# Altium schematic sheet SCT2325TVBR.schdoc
size 127 x 101 mm
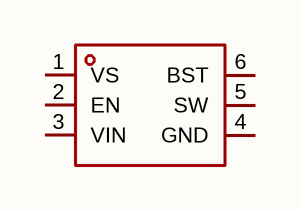
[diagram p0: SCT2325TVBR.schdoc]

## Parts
U?  sct2325tvbr  [TSOT-23-6_L2.9-W1.6-P0.95-LS2.8-BR]  (value not drawn)

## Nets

Not connected (* = marked no-connect by the designer): U? 1(VS) 2(EN) 3(VIN) 4(GND) 5(SW) 6(BST)

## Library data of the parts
U? = sct2325tvbr: 功能类型:降压型;工作电压:3.8V~32V;输出电压:5V;输出电流:2A;输出类型:固定;; Manufacturer: SCT(芯洲科技); AddInBom: yes; ModelId: 2c4039b5b88644c1bda4b4ba9e971667; ModelName: TSOT-23-6_L2.9-W1.6-H1.1-LS2.8-P0.95; ModelTransform: 110.45568,114.173,0,180,0,0,-0.005,-0.0005,0; Function: 降压型; Output Voltage: 5V; Output Current: 2A; Frequency - Switching: 1.1MHz; Synchronous Rectifier: 是; Number of Outputs: 1; Topology: 降压式; Quiescent Current: 20uA; Switch tube (built-in/external): 内置; Output Type: 固定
